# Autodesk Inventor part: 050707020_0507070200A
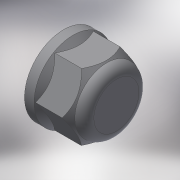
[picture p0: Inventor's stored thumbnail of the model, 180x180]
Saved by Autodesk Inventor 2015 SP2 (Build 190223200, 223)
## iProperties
Created: 2017-05
Part Number: 050707020_0507070200A
Material: Generic
Description: PLASSON CAP 2"
Document SubType Name: Modeling
Designer: KIM
Density: 1 g/cm^3
Appearance: Default
Author: KIM
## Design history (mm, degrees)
derived "050707.ipt"
feature "Solid1::050707.ipt"
tag "TaggingFeature1"
body "Solid1"
other parameters: "d0" = 39, "d1" = 2.5, "d2" = 56.656, "d3" = 25, "d4" = 2.5, "d5" = 135 deg, "d6" = 62.3216, "d8" = 68, "d9" = 65.6, "d10" = 135 deg, "d11" = 7.5, "d13" = 7.5, "d16" = 0, "Rp_" = 56.656, "H_" = 39, "l_2" = 25
